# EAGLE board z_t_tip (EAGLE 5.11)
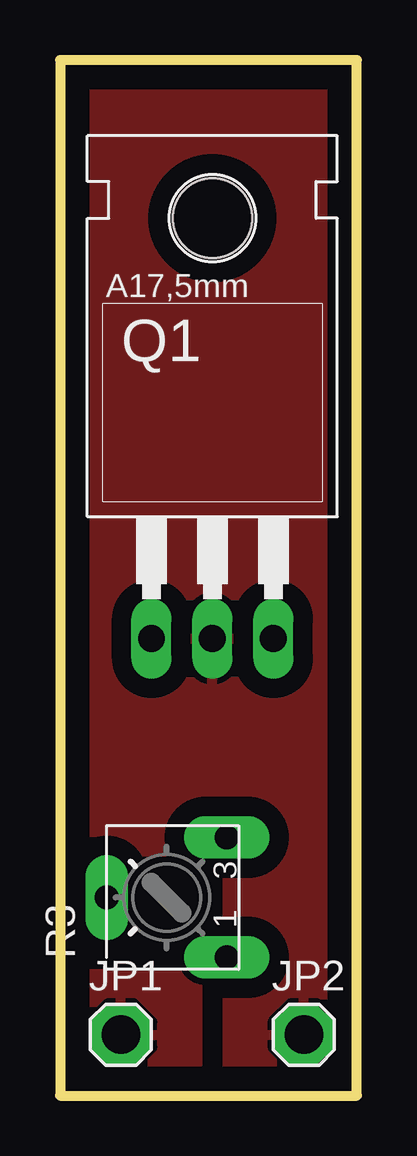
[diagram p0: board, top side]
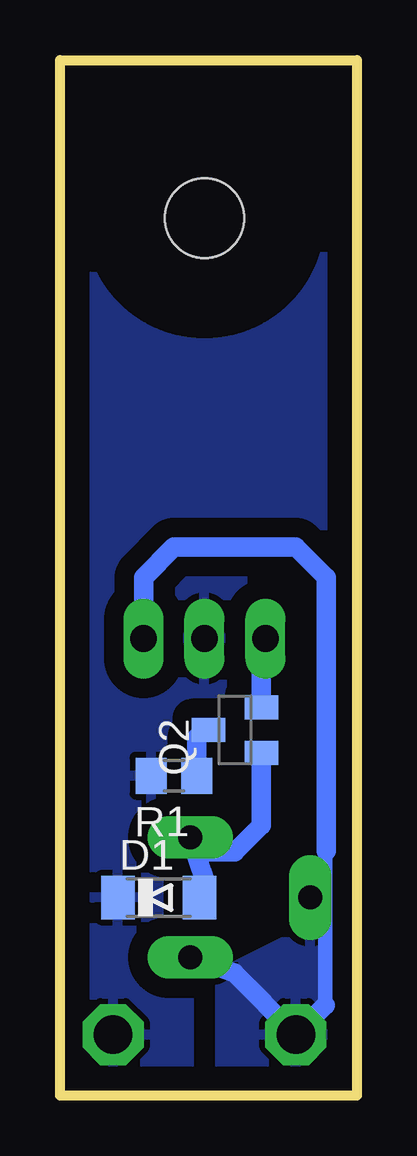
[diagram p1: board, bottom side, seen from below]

Size 12.37 x 43.17 mm. Coordinates in mm from the lower left corner, seen from the top.
Outline: 0,0 12.37,0 12.37,43.17 0,43.17 0,0
Copper layers (1*16): Top 0.035mm / dielectric 1.5mm / Bottom 0.035mm
Design rules "default": minimum track width 10mil, minimum drill 24mil, track to track 8mil, track to pad 8mil, pad to pad 8mil, via to via 8mil, smd to smd 8mil, copper to edge 40mil, drill to drill 8mil, minimum pad ring 10mil, minimum via ring 8mil, stop-mask expansion 4mil, vias tented up to drill 0mil, thermal gap 10mil

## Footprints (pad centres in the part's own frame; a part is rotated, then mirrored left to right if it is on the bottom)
MINIMELF = smd 1.4 x 1.8: A 1.7,0; C -1.7,0
1X1MM8 = drill 1.6 pad 2.54 octagon: 1 0,0
TO220 = drill 1.118 long: 1 -2.54,-6.35; 2 0,-6.35; 3 2.54,-6.35 | hole 3.302: 0,11.176
SOT23-BEC = smd 1 x 1.4: B -0.95,-1.1; C 0,1.1; E 0.95,-1.1
R0805 = smd 1.3 x 1.5: 1 -0.95,0; 2 0.95,0
EVND8AA = drill 1 pad 1.778 long: A -2.5,-2.5; E 2.5,-2.5; S 0,2.5

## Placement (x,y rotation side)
D1  [MINIMELF]  8.26,8.26 0 bottom
JP1  [1X1MM8]  2.54,2.54 0 top
JP2  [1X1MM8]  10.16,2.54 0 top
Q1  TIP122  [TO220]  6.35,25.4 0 top
Q2  BC817-16LT1SMD  [SOT23-BEC]  5.08,15.24 90 bottom
R1  [R0805]  7.62,13.34 180 bottom
R3  [EVND8AA]  4.45,8.26 90 top

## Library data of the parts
D1 = diode-1
JP1 JP2 = pinhead
Q1 Q2 = transistor-npn
R1 = rcl-2
R3 = pot

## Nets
C: D1.C JP2.1 Q1.2 R1.2
E-: JP1.1 Q1.3 R3.A R3.S
N$2: Q2.C R1.1
N$4: D1.A Q2.B R3.E
N$5: Q1.1 Q2.E

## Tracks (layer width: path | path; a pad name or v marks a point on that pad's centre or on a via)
C
  pour Bottom (isolate 0.813, rank 3): 1.27,39.37 10.16,39.37 11.43,38.1 11.43,1.27 6.99,1.27 6.99,10.16 1.27,10.16
  pour Top (isolate 0.813, rank 2): 1.27,41.91 11.43,41.91 11.43,1.27 6.99,1.27 6.99,10.16 1.27,10.16
E-
  Bottom 0.61: 1.31,3.77 1.31,10.16 1.27,10.2
  Bottom 0.813: 1.31,3.77 JP1.1 5.12,5.12 R3.A | Q1.3 8.89,21.59 7.62,22.86 2.54,22.86 1.27,21.59 1.27,10.2
  pour Bottom (isolate 0.813): 0.64,7.62 5.71,5.08 5.71,1.27 0.64,1.27
  pour Top (isolate 0.813): 1.27,5.08 5.71,5.08 5.71,1.27 1.27,1.27
N$2
  Bottom 0.813: R1.1 6.67,14.92 6.35,15.24 Q2.C
N$4
  Bottom 0.813: Q2.B 3.98,11.26 5.08,10.16 6.27,10.16 R3.E 6.31,8.93 6.35,8.89 6.35,8.46 D1.A
N$5
  Bottom 0.813: Q2.E 3.98,17.61 3.81,17.78 Q1.1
